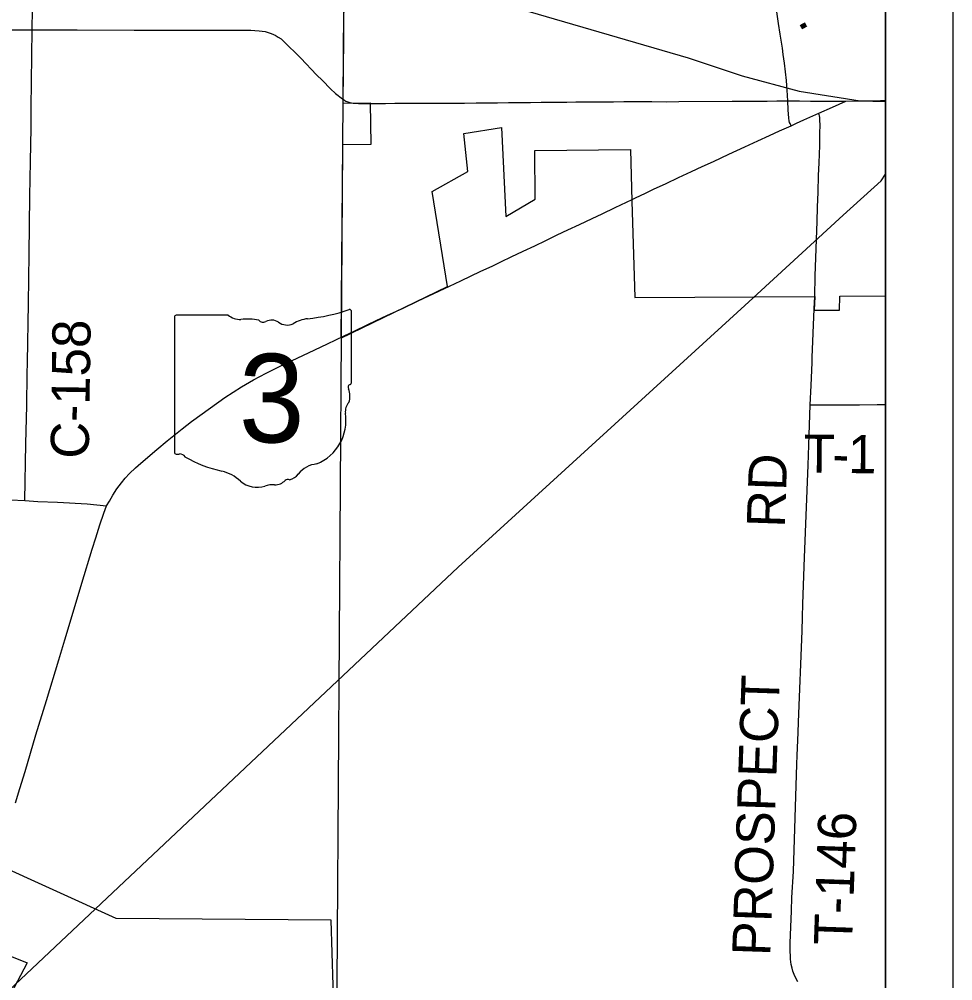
# Model space of a CAD drawing. Extents: x 0 to 34, y 0 to 22.
# Drawn here: x 25.1 to 26.49, y 3.831 to 5.262 of the extents above; entities that cross this region are included whole.
import ezdxf

# ---------------------------------------------------------------- set-up
doc = ezdxf.new("R2010")
doc.units = 0
for name, color, linetype in [('GM_X_Corporation', 7, 'Continuous'), ('GM_X_County_Road', 7, 'Continuous'), ('GM_X_County_Road_Text', 7, 'Continuous'), ('GM_X_Rail_Line', 7, 'Continuous'), ('GM_X_Rail_Line_Text', 7, 'Continuous'), ('GM_X_State_Location', 7, 'Continuous'), ('GM_X_State_Route', 7, 'Continuous'), ('GM_X_State_Shield', 7, 'Continuous'), ('GM_X_Township_Road', 7, 'Continuous'), ('GM_X_Township_Road_Text', 7, 'Continuous'), ('SH_Data', 7, 'Continuous')]:
    doc.layers.add(name, color=color, linetype=linetype)

msp = doc.modelspace()

# ---------------------------------------------------------------- linework, layer by layer
at = {"layer": 'GM_X_Corporation'}
for points in [[(25.5857, 5.6854), (25.5826, 5.2341), (25.5819, 5.1373), (25.6024, 5.1369), (25.6227, 5.1371), (25.6237, 5.0754), (25.5811, 5.075), (25.5789, 4.7872), (25.7378, 4.8637), (25.715, 5.0052), (25.7677, 5.0353), (25.762, 5.0918), (25.8182, 5.1004), (25.8244, 4.968), (25.8684, 4.9941), (25.8676, 5.0661), (26.01, 5.0678), (26.0123, 4.991), (26.0167, 4.8477), (26.2846, 4.8493), (26.2838, 4.8286), (26.3214, 4.8289), (26.3218, 4.8495), (26.39, 4.8499), (26.39, 6.8816)], [(25.5717, 3.6776), (25.5644, 3.9211), (25.2441, 3.9235), (25.0615, 4.0064), (25.0753, 4.0494), (24.8686, 4.1001), (24.8583, 3.9816), (24.9249, 3.956), (24.9362, 3.9854), (25.0563, 3.9875), (25.0263, 3.8917), (25.1115, 3.8574), (25.0873, 3.8111)]]:
    msp.add_lwpolyline(points, dxfattribs=at)
at = {"layer": 'GM_X_County_Road'}
for p, q in [((25.5847, 5.1408), (25.5864, 5.1397)), ((25.7123, 5.1366), (25.7455, 5.1367))]:
    msp.add_line(p, q, dxfattribs=at)
for points in [[(25.1084, 4.5453), (25.1095, 4.6298), (25.111, 4.6869), (25.1117, 4.7335), (25.112, 4.7515), (25.1137, 4.8386), (25.1148, 4.9119), (25.1159, 4.9982), (25.1168, 5.05), (25.1175, 5.1003), (25.1177, 5.1299), (25.1192, 5.246), (25.1199, 5.2765), (25.121, 5.3266), (25.1218, 5.4013), (25.1233, 5.5472), (25.1239, 5.5934), (25.1256, 5.7301), (25.1266, 5.8167), (25.1275, 5.877), (25.1284, 5.9526), (25.1288, 5.9608), (25.1299, 5.9663)], [(26.2363, 5.2185), (26.2355, 5.2245), (26.2331, 5.2394), (26.2306, 5.2553), (26.2278, 5.2725)], [(25.0595, 5.2461), (25.1192, 5.246), (25.1861, 5.2458), (25.2709, 5.2456), (25.3652, 5.2453), (25.3847, 5.2455), (25.4016, 5.2456), (25.4449, 5.2453), (25.4507, 5.2451), (25.4573, 5.2443), (25.4662, 5.2432), (25.4705, 5.2419), (25.475, 5.2405), (25.4784, 5.2391), (25.481, 5.238), (25.4854, 5.2352), (25.4897, 5.2323), (25.4931, 5.2295), (25.519, 5.2039), (25.5427, 5.1792), (25.5516, 5.1703), (25.5636, 5.158), (25.5708, 5.1511), (25.5812, 5.143), (25.5847, 5.1408)], [(26.2442, 5.1403), (26.2433, 5.1562), (26.2423, 5.1704), (26.2411, 5.1836), (26.2393, 5.1964), (26.2375, 5.2094), (26.2363, 5.2185)], [(25.5864, 5.1397), (25.592, 5.1378), (25.5973, 5.1366), (25.6053, 5.1362), (25.6241, 5.1361)], [(25.7455, 5.1367), (25.7465, 5.1367), (25.7631, 5.1369), (25.7804, 5.1371), (25.797, 5.1373), (25.812, 5.1375), (25.8284, 5.1376), (25.8445, 5.1378), (25.8614, 5.138), (25.877, 5.1382), (25.8944, 5.1384), (25.9152, 5.1385), (25.9287, 5.1386), (25.9456, 5.1387), (25.9644, 5.1388), (25.9811, 5.1389), (25.985, 5.139)], [(25.985, 5.139), (26, 5.1391), (26.0228, 5.1392), (26.0421, 5.1393), (26.0631, 5.139), (26.0821, 5.1393), (26.1615, 5.1396), (26.1793, 5.1398), (26.1882, 5.1399)], [(26.1882, 5.1399), (26.2138, 5.14), (26.2281, 5.1401), (26.2442, 5.1403), (26.2619, 5.1401), (26.2781, 5.14), (26.295, 5.1398), (26.3128, 5.1396), (26.3309, 5.1398)], [(26.2492, 5.1033), (26.2477, 5.1066), (26.2471, 5.1081), (26.2464, 5.1107), (26.2459, 5.1146), (26.2451, 5.127), (26.2442, 5.1403)], [(25.6241, 5.1361), (25.6452, 5.1364), (25.6592, 5.1367)], [(25.6592, 5.1367), (25.6679, 5.1368), (25.6894, 5.1367), (25.7123, 5.1366)], [(25.1084, 4.5453), (25.1277, 4.5441), (25.157, 4.5429), (25.2013, 4.5404), (25.2301, 4.5377)]]:
    msp.add_lwpolyline(points, dxfattribs=at)
at = {"layer": 'GM_X_Rail_Line'}
msp.add_lwpolyline([(26.39, 3.6678), (26.39, 8.7517), (26.3812, 8.7517), (25.61, 8.7495), (25.6021, 8.0258), (25.6016, 7.958), (25.5949, 6.9989), (25.5948, 6.9859), (25.5947, 6.9673), (25.5942, 6.8999), (25.594, 6.873), (25.5922, 6.6163), (25.5923, 6.6046), (25.5921, 6.5988), (25.5865, 5.8006), (25.582, 5.143), (25.5795, 4.789), (25.5717, 3.6776), (26.3477, 3.6686)], close=True, dxfattribs=at)
for points in [[(24.9002, 5.409), (25.2202, 5.3968), (25.3596, 5.3828), (25.4573, 5.3668), (25.5477, 5.3475), (25.6871, 5.3184), (25.8181, 5.285), (25.9512, 5.2463), (26.096, 5.2045), (26.1762, 5.1775), (26.2614, 5.1546), (26.3521, 5.1403), (26.39, 5.1394)], [(24.9499, 3.6844), (24.9615, 3.7017), (24.9988, 3.7358), (25.7536, 4.446), (26.1804, 4.8358), (26.3268, 4.9703), (26.3834, 5.0214), (26.39, 5.0313)]]:
    msp.add_lwpolyline(points, dxfattribs=at)
at = {"layer": 'GM_X_State_Route'}
for p, q in [((26.3822, 5.1406), (26.39, 5.1406)), ((26.0126, 4.9932), (26.0178, 4.9958))]:
    msp.add_line(p, q, dxfattribs=at)
for points in [[(26.2574, 5.1071), (26.2684, 5.1121), (26.2904, 5.1221), (26.3109, 5.131), (26.3309, 5.1398)], [(26.3309, 5.1398), (26.3464, 5.1401), (26.3642, 5.1405), (26.3822, 5.1406)], [(26.0178, 4.9958), (26.0327, 5.0029), (26.0446, 5.0086), (26.0633, 5.0173), (26.0817, 5.026), (26.1009, 5.035), (26.117, 5.0424), (26.1335, 5.0501), (26.1563, 5.0607), (26.1804, 5.0718), (26.1997, 5.0806), (26.2169, 5.0885), (26.2319, 5.0954), (26.2492, 5.1033), (26.2574, 5.1071)], [(25.7404, 4.8643), (25.7573, 4.8723), (25.7875, 4.8866), (25.8041, 4.8944), (25.8179, 4.9011), (25.8325, 4.908), (25.8503, 4.9165), (25.8676, 4.9247), (25.884, 4.9325), (25.9011, 4.9406), (25.917, 4.9481), (25.9341, 4.9563), (25.9528, 4.9651), (25.968, 4.9723), (25.9871, 4.9813), (26.0126, 4.9932)], [(25.5838, 4.7905), (25.5987, 4.7976), (25.6179, 4.8067), (25.6314, 4.8131), (25.6483, 4.8211), (25.6704, 4.8314), (25.6941, 4.8425), (25.7173, 4.8534), (25.7404, 4.8643)], [(25.0944, 4.0953), (25.1009, 4.1167), (25.1086, 4.1423), (25.1247, 4.1969), (25.1404, 4.2478), (25.1589, 4.3082), (25.1676, 4.338), (25.1757, 4.3643), (25.1933, 4.4226), (25.2087, 4.4732), (25.2139, 4.4901), (25.2199, 4.5094), (25.2258, 4.5264), (25.2301, 4.5377), (25.2342, 4.5445), (25.2394, 4.5534), (25.2453, 4.5627), (25.2521, 4.5719), (25.2576, 4.5786), (25.264, 4.5854), (25.273, 4.5941), (25.281, 4.601), (25.3047, 4.6214), (25.3201, 4.6341), (25.3424, 4.6519), (25.3565, 4.663), (25.3845, 4.6835), (25.406, 4.6987), (25.4309, 4.7147), (25.4485, 4.725), (25.4674, 4.7351), (25.4894, 4.746), (25.5307, 4.7654), (25.5589, 4.7788), (25.5838, 4.7905)]]:
    msp.add_lwpolyline(points, dxfattribs=at)
at = {"layer": 'GM_X_State_Shield'}
for p, q in [((25.5947, 4.7216), (25.5947, 4.8263)), ((25.331, 4.8179), (25.331, 4.6178)), ((25.4109, 4.8213), (25.3336, 4.8213)), ((25.5947, 4.7216), (25.5947, 4.7216))]:
    msp.add_line(p, q, dxfattribs=at)
for centre, radius, start, end in [((25.5008, 5.0942), 0.2796, 275.8445, 288.9065), ((25.5918, 4.8267), 0.00294, 351.8621, 97.738), ((25.3341, 4.8183), 0.00305, 98.1301, 188.1301), ((25.4292, 4.8446), 0.0296, 231.6195, 271.1119), ((25.4391, 4.709), 0.1064, 80.4867, 94.9883), ((25.4632, 4.8194), 0.00855, 219.7921, 297.1024), ((25.4758, 4.7962), 0.0178, 54.4667, 119.1411), ((25.4987, 4.828), 0.0214, 233.8562, 294.8282), ((25.5365, 4.7602), 0.0563, 97.3462, 120.7689), ((25.594, 4.7139), 0.00454, 107.944, 210.337), ((25.5651, 4.7007), 0.0273, 340.033, 23.6496), ((25.5916, 4.7212), 0.00314, 289.6038, 7.7341), ((25.6052, 4.6778), 0.0198, 136.8065, 186.9296), ((25.5165, 4.6645), 0.0699, 292.3089, 8.9858), ((25.3341, 4.6173), 0.00308, 171.9584, 258.3066), ((25.3346, 4.6378), 0.0235, 267.339, 280.6039), ((25.3394, 4.6062), 0.00848, 29.7484, 93.2717), ((25.4464, 4.786), 0.2019, 240.4129, 257.1985), ((25.5459, 4.5616), 0.0383, 94.4031, 142.5768), ((25.3862, 4.5279), 0.0632, 47.1842, 75.836), ((25.4974, 4.5984), 0.0226, 282.8732, 323.2771), ((25.4546, 4.6052), 0.0401, 230.7004, 286.2918), ((25.4777, 4.5361), 0.0329, 85.6951, 111.2099), ((25.4807, 4.5903), 0.0214, 268.777, 315.5493), ((25.5, 4.5709), 0.00601, 65.7517, 132.6484)]:
    msp.add_arc(centre, radius, start, end, dxfattribs=at)
at = {"layer": 'GM_X_Township_Road'}
msp.add_line((26.2837, 4.8306), (26.2844, 4.8492), dxfattribs=at)
for points in [[(26.2918, 5.0738), (26.2921, 5.0923), (26.2923, 5.1041), (26.2922, 5.1113), (26.2918, 5.1153), (26.2914, 5.1179), (26.2904, 5.1221)], [(26.2844, 4.8492), (26.2853, 4.8797), (26.2862, 4.9067), (26.287, 4.9341), (26.2879, 4.9609), (26.2886, 4.982), (26.2894, 5.0044), (26.2903, 5.0292), (26.2909, 5.048), (26.2918, 5.0738)], [(26.2592, 3.8289), (26.2557, 3.8357), (26.2538, 3.8399), (26.2519, 3.8451), (26.2507, 3.8492), (26.2496, 3.8548), (26.2486, 3.863), (26.2482, 3.8676), (26.248, 3.8741), (26.248, 3.8866), (26.2498, 3.9348), (26.2505, 3.9546), (26.2526, 3.9934), (26.2578, 4.1528), (26.2583, 4.166), (26.2596, 4.2), (26.2601, 4.2155), (26.2656, 4.3516), (26.266, 4.3718), (26.2668, 4.3916), (26.2694, 4.4605), (26.2747, 4.5978), (26.2756, 4.6279), (26.2778, 4.6878), (26.279, 4.7165), (26.2805, 4.7508), (26.2808, 4.7584), (26.2837, 4.8306)], [(26.2778, 4.6878), (26.351, 4.6877), (26.3775, 4.6881), (26.39, 4.6883)], [(25.0649, 4.5475), (25.1084, 4.5453)]]:
    msp.add_lwpolyline(points, dxfattribs=at)
at = {"layer": 'SH_Data'}
for p, q in [((26.49, 10.5678), (26.49, 3.5678)), ((26.39, 10.4678), (26.39, 3.6678))]:
    msp.add_line(p, q, dxfattribs=at)

# ---------------------------------------------------------------- texts
at = {"layer": 'GM_X_County_Road_Text'}
msp.add_text('C-158', height=0.05682, rotation=89.1741, dxfattribs=at).set_placement((25.2034, 4.6074))
at = {"layer": 'GM_X_Rail_Line_Text'}
msp.add_text('.', height=0.0566, rotation=298.5307, dxfattribs=at).set_placement((26.2588, 5.259))
at = {"layer": 'GM_X_State_Location'}
for s in ['s', 'r']:
    msp.add_text(s, height=0.000189, dxfattribs=at).set_placement((25.4599, 4.7045))
msp.add_text('3', height=0.000189, rotation=0, dxfattribs=at).set_placement((25.4314, 4.6908))
at = {"layer": 'GM_X_State_Shield'}
msp.add_text('3', height=0.1318, dxfattribs=at).set_placement((25.4268, 4.6319))
at = {"layer": 'GM_X_Township_Road_Text'}
for s, height, rotation, p in [('T', 0.0568, 359.3786, (26.2678, 4.5869)), ('1', 0.0568, 359.6432, (26.3339, 4.5862)), ('RD', 0.05682, 88.0243, (26.2399, 4.5046)), ('-', 0.0568, 359.4382, (26.3104, 4.5864)), ('PROSPECT', 0.05682, 88.0538, (26.2182, 3.8671)), ('T-146', 0.05682, 88.0347, (26.3399, 3.8829))]:
    msp.add_text(s, height=height, rotation=rotation, dxfattribs=at).set_placement(p)

doc.saveas('drawing.dxf')
